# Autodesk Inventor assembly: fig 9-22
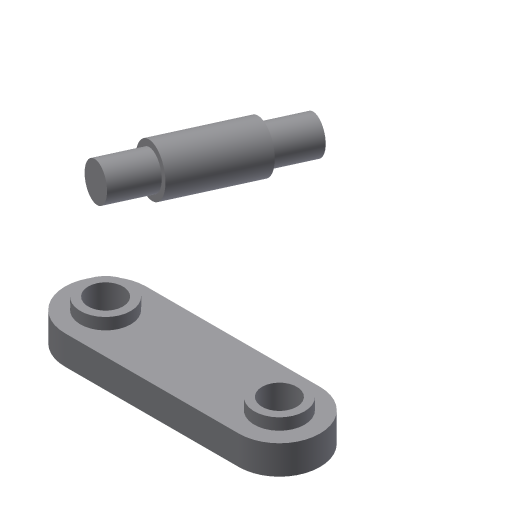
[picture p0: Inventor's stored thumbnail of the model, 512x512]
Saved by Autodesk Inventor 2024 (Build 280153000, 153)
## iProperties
Shininess: 64.0
Length Units: 11269
Angle Units: 11279
Time Units: 11290
Mass Units: 11283
Length Display Precision: 3
Angle Display Precision: 2
Created: 2002-01
Part Number: fig 9-22
Document SubType Name: Assembly
Designer: ***
Density: 0.0
Volumn: 0.0
Area: 0.0
PropertySet Name: Model Information
Control State: 0
Master: False
Checked Out: False
Author: ***
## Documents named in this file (3)
- D:\PROJECTS\Project 2023\RESOURCES INVENTOR 2024\RESOURCES INVENTOR 2024\Inventor_2023_Part\Inventor_2024_Part\c09_Inv_2024_prt\fig 9-22.iam
- D:\PROJECTS\Project 2023\RESOURCES INVENTOR 2024\RESOURCES INVENTOR 2024\Inventor_2023_Part\Inventor_2024_Part\c09_Inv_2024_prt\Part5.ipt
- D:\PROJECTS\Project 2023\RESOURCES INVENTOR 2024\RESOURCES INVENTOR 2024\Inventor_2023_Part\Inventor_2024_Part\c09_Inv_2024_prt\Part6.ipt
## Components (2 placed, 2 different names)
1. Part5:1
2. Part6:1
